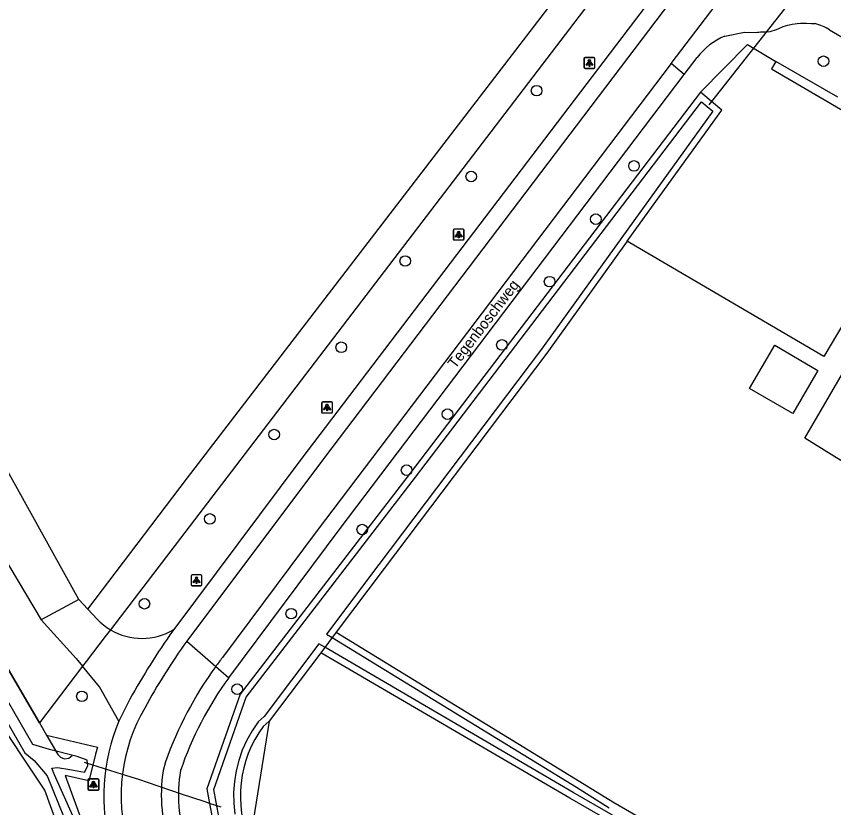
# Model space of a CAD drawing. Extents: x 156502 to 159074, y 384229 to 386094.
# Drawn here: x 157013.2 to 157088.8, y 385827.5 to 385900.5 of the extents above; entities that cross this region are included whole.
import ezdxf

# ---------------------------------------------------------------- set-up
doc = ezdxf.new("R2010")
doc.units = 0
for name, color, linetype in [('IMGEO_Berm_groen', 7, 'Continuous'), ('IMGEO_Berm_halfverhard', 7, 'Continuous'), ('IMGEO_Boom', 7, 'Continuous'), ('IMGEO_Duiker', 7, 'Continuous'), ('IMGEO_Erf', 7, 'Continuous'), ('IMGEO_Groenvoorziening', 7, 'Continuous'), ('IMGEO_Haag', 7, 'Continuous'), ('IMGEO_Hek', 7, 'Continuous'), ('IMGEO_Lichtpunt', 7, 'Continuous'), ('IMGEO_Loofbos', 7, 'Continuous'), ('IMGEO_Openbare_ruimte_label', 7, 'Continuous'), ('IMGEO_Pand', 7, 'Continuous'), ('IMGEO_Rijbaan_lokaal_gesloten', 7, 'Continuous'), ('IMGEO_Rijbaan_lokaal_halfverhard', 7, 'Continuous'), ('IMGEO_Waterloop', 7, 'Continuous')]:
    doc.layers.add(name, color=color, linetype=linetype)

msp = doc.modelspace()

# ---------------------------------------------------------------- linework, layer by layer
at = {"layer": 'IMGEO_Berm_groen'}
msp.add_lwpolyline([(157184.907, 386057.234), (157021.918, 385843.894)], dxfattribs=at)
at = {"layer": 'IMGEO_Berm_halfverhard'}
for points in [[(157188.566, 386055.162), (157076.319, 385908.026), (157039.623, 385859.739), (157027.777, 385843.918)], [(157032.855, 385839.465), (157043.149, 385853.233), (157074.946, 385895.192)]]:
    msp.add_lwpolyline(points, dxfattribs=at)
msp.add_arc((157039.111, 385828.542), 17.804, 157.16468, 195.80884, dxfattribs=at)
at = {"layer": 'IMGEO_Boom'}
for centre in [(157087.82, 385896.404), (157061.306, 385893.682), (157070.302, 385886.733), (157055.263, 385885.754), (157066.776, 385881.815), (157049.163, 385877.949), (157062.506, 385876.047), (157043.253, 385869.983), (157058.102, 385870.199), (157053.074, 385863.804), (157037.054, 385861.923), (157049.291, 385858.635), (157031.106, 385854.129), (157045.19, 385853.148), (157025.065, 385846.293), (157038.63, 385845.375), (157033.63, 385838.407), (157019.285, 385837.744)]:
    msp.add_circle(centre, 0.489, dxfattribs=at)
at = {"layer": 'IMGEO_Duiker'}
for points in [[(157094.166, 385913.916), (157093.864, 385913.531), (157090.745, 385909.563), (157082.608, 385899.211), (157077.479, 385892.687), (157077.23, 385892.37)], [(157032.147, 385827.513), (157031.672, 385827.668), (157031.084, 385827.859), (157030.686, 385827.989), (157029.45, 385828.392), (157028.575, 385828.678), (157026.335, 385829.441), (157024.544, 385830.051), (157023.026, 385830.525), (157020.689, 385831.254), (157020.295, 385831.377), (157019.534, 385831.625)]]:
    msp.add_lwpolyline(points, dxfattribs=at)
at = {"layer": 'IMGEO_Erf'}
msp.add_lwpolyline([(157069.688, 385879.771), (157062.244, 385869.451), (157047.224, 385849.55), (157042.786, 385843.67), (157065.314, 385829.887), (157068.346, 385827.983), (157173.435, 385767.228), (157172.677, 385766.006), (157064.372, 385828.327), (157041.356, 385841.775), (157036.588, 385835.458)], dxfattribs=at)
at = {"layer": 'IMGEO_Groenvoorziening'}
for points in [[(157019.844, 385845.786), (157029.054, 385857.935), (157071.087, 385912.699), (157180.634, 386056.206), (157157.667, 386069.213), (157141.859, 386060.718)], [(157015.352, 385835.3), (157000, 385861.546), (156954.711, 385939.318)], [(157076.448, 385893.546), (157080.786, 385897.944), (157083.416, 385896.387)], [(157076.448, 385893.546), (157049.627, 385858.357), (157033.907, 385837.957), (157030.83, 385829.194), (157031.084, 385827.859), (157032.23, 385821.835), (157037.896, 385808.02), (157042.738, 385795.688), (157045.399, 385797.293)], [(157069.688, 385879.771), (157078.432, 385891.893), (157077.479, 385892.687), (157076.448, 385893.546)], [(157105.837, 385870.09), (157092.904, 385877.624), (157087.856, 385869.139), (157069.928, 385879.631), (157069.688, 385879.771)], [(157019.342, 385840.522), (157015.352, 385835.3)], [(157015.352, 385835.3), (157016.015, 385834.166), (157020.718, 385833.042), (157020.555, 385832.399), (157020.295, 385831.377), (157019.932, 385829.949), (157017.732, 385830.418), (157029.334, 385798.749)], [(157036.588, 385835.458), (157034.974, 385825.476), (157048.314, 385802.061)], [(157036.041, 385834.964), (157036.588, 385835.458)]]:
    msp.add_lwpolyline(points, dxfattribs=at)
msp.add_arc((157044.63, 385828.574), 10.705, 143.35, 203.97313, dxfattribs=at)
at = {"layer": 'IMGEO_Haag'}
for points in [[(157083.416, 385896.387), (157083.012, 385895.697), (157110.374, 385879.708), (157105.763, 385871.809), (157093.618, 385878.818), (157093.206, 385878.142), (157106.141, 385870.607)], [(157089.134, 385893.087), (157083.416, 385896.387)]]:
    msp.add_lwpolyline(points, dxfattribs=at)
at = {"layer": 'IMGEO_Hek'}
for points in [[(157069.928, 385879.631), (157069.688, 385879.771)], [(157105.837, 385870.09), (157092.904, 385877.624), (157087.856, 385869.139), (157069.928, 385879.631)], [(157062.244, 385869.451), (157047.224, 385849.55)], [(157000, 385861.546), (157015.352, 385835.3)], [(157047.224, 385849.55), (157042.786, 385843.67)], [(157042.786, 385843.67), (157041.356, 385841.775)], [(157041.356, 385841.775), (157036.588, 385835.458)], [(157015.352, 385835.3), (157016.015, 385834.166)], [(157036.588, 385835.458), (157034.974, 385825.476), (157048.314, 385802.061)], [(157016.015, 385834.166), (157017.071, 385832.361)], [(157017.071, 385832.361), (157017.295, 385832.115), (157017.683, 385831.969), (157018.092, 385832.037), (157018.396, 385832.278)]]:
    msp.add_lwpolyline(points, dxfattribs=at)
at = {"layer": 'IMGEO_Lichtpunt'}
for p, q in [((157065.684, 385896.653), (157065.684, 385895.846)), ((157065.684, 385896.653), (157065.684, 385895.846)), ((157065.69, 385896.625), (157065.69, 385895.818)), ((157065.69, 385896.625), (157065.69, 385895.818)), ((157066.586, 385896.748), (157065.778, 385896.748)), ((157066.586, 385896.748), (157065.778, 385896.748)), ((157066.592, 385896.72), (157065.784, 385896.72)), ((157066.592, 385896.72), (157065.784, 385896.72)), ((157066.68, 385895.846), (157066.68, 385896.653)), ((157066.68, 385895.846), (157066.68, 385896.653)), ((157066.686, 385895.818), (157066.686, 385896.625)), ((157066.686, 385895.818), (157066.686, 385896.625)), ((157065.778, 385895.752), (157066.586, 385895.752)), ((157065.778, 385895.752), (157066.586, 385895.752)), ((157065.784, 385895.724), (157066.592, 385895.724)), ((157065.784, 385895.724), (157066.592, 385895.724)), ((157053.595, 385880.794), (157053.595, 385879.987)), ((157053.595, 385880.794), (157053.595, 385879.987)), ((157053.621, 385880.81), (157053.621, 385880.003)), ((157053.621, 385880.81), (157053.621, 385880.003)), ((157054.497, 385880.889), (157053.689, 385880.889)), ((157054.497, 385880.889), (157053.689, 385880.889)), ((157054.523, 385880.905), (157053.715, 385880.905)), ((157054.523, 385880.905), (157053.715, 385880.905)), ((157054.591, 385879.987), (157054.591, 385880.794)), ((157054.591, 385879.987), (157054.591, 385880.794)), ((157054.617, 385880.003), (157054.617, 385880.81)), ((157054.617, 385880.003), (157054.617, 385880.81)), ((157053.689, 385879.893), (157054.497, 385879.893)), ((157053.689, 385879.893), (157054.497, 385879.893)), ((157053.715, 385879.909), (157054.523, 385879.909)), ((157053.715, 385879.909), (157054.523, 385879.909)), ((157041.435, 385864.817), (157041.435, 385864.01)), ((157041.435, 385864.817), (157041.435, 385864.01)), ((157041.444, 385864.835), (157041.444, 385864.028)), ((157041.444, 385864.835), (157041.444, 385864.028)), ((157042.337, 385864.912), (157041.529, 385864.912)), ((157042.337, 385864.912), (157041.529, 385864.912)), ((157042.346, 385864.93), (157041.538, 385864.93)), ((157042.346, 385864.93), (157041.538, 385864.93)), ((157042.431, 385864.01), (157042.431, 385864.817)), ((157042.431, 385864.01), (157042.431, 385864.817)), ((157042.44, 385864.028), (157042.44, 385864.835)), ((157042.44, 385864.028), (157042.44, 385864.835)), ((157041.529, 385863.916), (157042.337, 385863.916)), ((157041.529, 385863.916), (157042.337, 385863.916)), ((157041.538, 385863.934), (157042.346, 385863.934)), ((157041.538, 385863.934), (157042.346, 385863.934)), ((157029.374, 385848.856), (157029.374, 385848.049)), ((157029.374, 385848.856), (157029.374, 385848.049)), ((157029.381, 385848.881), (157029.381, 385848.074)), ((157029.381, 385848.881), (157029.381, 385848.074)), ((157030.276, 385848.951), (157029.468, 385848.951)), ((157030.276, 385848.951), (157029.468, 385848.951)), ((157030.283, 385848.976), (157029.475, 385848.976)), ((157030.283, 385848.976), (157029.475, 385848.976)), ((157030.37, 385848.049), (157030.37, 385848.856)), ((157030.37, 385848.049), (157030.37, 385848.856)), ((157030.377, 385848.074), (157030.377, 385848.881)), ((157030.377, 385848.074), (157030.377, 385848.881)), ((157029.468, 385847.955), (157030.276, 385847.955)), ((157029.468, 385847.955), (157030.276, 385847.955)), ((157029.475, 385847.98), (157030.283, 385847.98)), ((157029.475, 385847.98), (157030.283, 385847.98)), ((157019.842, 385829.989), (157019.842, 385829.182)), ((157019.842, 385829.989), (157019.842, 385829.182)), ((157019.845, 385830.016), (157019.845, 385829.209)), ((157019.845, 385830.016), (157019.845, 385829.209)), ((157019.877, 385829.983), (157019.877, 385829.176)), ((157019.877, 385829.983), (157019.877, 385829.176)), ((157020.744, 385830.084), (157019.936, 385830.084)), ((157020.744, 385830.084), (157019.936, 385830.084)), ((157020.747, 385830.111), (157019.939, 385830.111)), ((157020.747, 385830.111), (157019.939, 385830.111)), ((157020.779, 385830.078), (157019.971, 385830.078)), ((157020.779, 385830.078), (157019.971, 385830.078)), ((157020.838, 385829.182), (157020.838, 385829.989)), ((157020.838, 385829.182), (157020.838, 385829.989)), ((157020.841, 385829.209), (157020.841, 385830.016)), ((157020.841, 385829.209), (157020.841, 385830.016)), ((157020.873, 385829.176), (157020.873, 385829.983)), ((157020.873, 385829.176), (157020.873, 385829.983)), ((157019.936, 385829.088), (157020.744, 385829.088)), ((157019.936, 385829.088), (157020.744, 385829.088)), ((157019.939, 385829.115), (157020.747, 385829.115)), ((157019.939, 385829.115), (157020.747, 385829.115)), ((157019.971, 385829.082), (157020.779, 385829.082)), ((157019.971, 385829.082), (157020.779, 385829.082))]:
    msp.add_line(p, q, dxfattribs=at)
for points in [[(157066.058, 385896.317), (157066.097, 385896.289), (157065.909, 385896.027), (157065.871, 385896.054), (157066.058, 385896.317)], [(157066.064, 385896.289), (157066.103, 385896.261), (157065.915, 385895.999), (157065.877, 385896.026), (157066.064, 385896.289)], [(157066.16, 385896.269), (157066.207, 385896.269), (157066.207, 385895.947), (157066.16, 385895.947), (157066.16, 385896.269)], [(157066.166, 385896.241), (157066.213, 385896.241), (157066.213, 385895.919), (157066.166, 385895.919), (157066.166, 385896.241)], [(157066.27, 385896.289), (157066.308, 385896.316), (157066.495, 385896.054), (157066.456, 385896.026), (157066.27, 385896.289)], [(157066.276, 385896.261), (157066.314, 385896.288), (157066.501, 385896.026), (157066.462, 385895.998), (157066.276, 385896.261)], [(157053.969, 385880.458), (157054.008, 385880.43), (157053.82, 385880.168), (157053.782, 385880.195), (157053.969, 385880.458)], [(157053.995, 385880.474), (157054.034, 385880.446), (157053.846, 385880.184), (157053.808, 385880.211), (157053.995, 385880.474)], [(157054.071, 385880.41), (157054.118, 385880.41), (157054.118, 385880.088), (157054.071, 385880.088), (157054.071, 385880.41)], [(157054.097, 385880.426), (157054.144, 385880.426), (157054.144, 385880.104), (157054.097, 385880.104), (157054.097, 385880.426)], [(157054.181, 385880.43), (157054.219, 385880.457), (157054.406, 385880.195), (157054.367, 385880.167), (157054.181, 385880.43)], [(157054.207, 385880.446), (157054.245, 385880.473), (157054.432, 385880.211), (157054.393, 385880.183), (157054.207, 385880.446)], [(157041.809, 385864.481), (157041.848, 385864.453), (157041.66, 385864.191), (157041.622, 385864.218), (157041.809, 385864.481)], [(157041.818, 385864.499), (157041.857, 385864.471), (157041.669, 385864.209), (157041.631, 385864.236), (157041.818, 385864.499)], [(157041.911, 385864.433), (157041.958, 385864.433), (157041.958, 385864.111), (157041.911, 385864.111), (157041.911, 385864.433)], [(157041.92, 385864.451), (157041.967, 385864.451), (157041.967, 385864.129), (157041.92, 385864.129), (157041.92, 385864.451)], [(157042.021, 385864.453), (157042.059, 385864.48), (157042.246, 385864.218), (157042.207, 385864.19), (157042.021, 385864.453)], [(157042.03, 385864.471), (157042.068, 385864.498), (157042.255, 385864.236), (157042.216, 385864.208), (157042.03, 385864.471)], [(157029.755, 385848.545), (157029.794, 385848.517), (157029.606, 385848.255), (157029.568, 385848.282), (157029.755, 385848.545)], [(157029.967, 385848.517), (157030.005, 385848.544), (157030.192, 385848.282), (157030.153, 385848.254), (157029.967, 385848.517)], [(157029.748, 385848.52), (157029.787, 385848.492), (157029.599, 385848.23), (157029.561, 385848.257), (157029.748, 385848.52)], [(157029.85, 385848.472), (157029.897, 385848.472), (157029.897, 385848.15), (157029.85, 385848.15), (157029.85, 385848.472)], [(157029.857, 385848.497), (157029.904, 385848.497), (157029.904, 385848.175), (157029.857, 385848.175), (157029.857, 385848.497)], [(157029.96, 385848.492), (157029.998, 385848.519), (157030.185, 385848.257), (157030.146, 385848.229), (157029.96, 385848.492)], [(157020.216, 385829.653), (157020.255, 385829.625), (157020.067, 385829.363), (157020.029, 385829.39), (157020.216, 385829.653)], [(157020.219, 385829.68), (157020.258, 385829.652), (157020.07, 385829.39), (157020.032, 385829.417), (157020.219, 385829.68)], [(157020.251, 385829.647), (157020.29, 385829.619), (157020.102, 385829.357), (157020.064, 385829.384), (157020.251, 385829.647)], [(157020.428, 385829.625), (157020.466, 385829.652), (157020.653, 385829.39), (157020.614, 385829.362), (157020.428, 385829.625)], [(157020.431, 385829.652), (157020.469, 385829.679), (157020.656, 385829.417), (157020.617, 385829.389), (157020.431, 385829.652)], [(157020.463, 385829.619), (157020.501, 385829.646), (157020.688, 385829.384), (157020.649, 385829.356), (157020.463, 385829.619)], [(157020.318, 385829.605), (157020.365, 385829.605), (157020.365, 385829.283), (157020.318, 385829.283), (157020.318, 385829.605)], [(157020.321, 385829.632), (157020.368, 385829.632), (157020.368, 385829.31), (157020.321, 385829.31), (157020.321, 385829.632)], [(157020.353, 385829.599), (157020.4, 385829.599), (157020.4, 385829.277), (157020.353, 385829.277), (157020.353, 385829.599)]]:
    msp.add_lwpolyline(points, dxfattribs=at)
for centre in [(157066.183, 385896.451), (157066.189, 385896.423), (157054.094, 385880.592), (157054.12, 385880.608), (157041.934, 385864.615), (157041.943, 385864.633), (157029.873, 385848.654), (157029.88, 385848.679), (157020.341, 385829.787), (157020.344, 385829.814), (157020.376, 385829.781)]:
    msp.add_circle(centre, 0.0994, dxfattribs=at)
for centre, start, end in [((157065.778, 385896.653), 90, 180), ((157065.778, 385896.653), 90, 180), ((157065.784, 385896.625), 90, 180), ((157065.784, 385896.625), 90, 180), ((157066.586, 385896.653), 0, 90), ((157066.586, 385896.653), 0, 90), ((157066.592, 385896.625), 0, 90), ((157066.592, 385896.625), 0, 90), ((157065.778, 385895.846), 180, 270), ((157065.778, 385895.846), 180, 270), ((157065.784, 385895.818), 180, 270), ((157065.784, 385895.818), 180, 270), ((157066.586, 385895.846), 270, 0), ((157066.586, 385895.846), 270, 360), ((157066.592, 385895.818), 270, 0), ((157066.592, 385895.818), 270, 360), ((157053.689, 385880.794), 90, 180), ((157053.689, 385880.794), 90, 180), ((157053.715, 385880.81), 90, 180), ((157053.715, 385880.81), 90, 180), ((157054.497, 385880.794), 0, 90), ((157054.497, 385880.794), 0, 90), ((157054.523, 385880.81), 0, 90), ((157054.523, 385880.81), 0, 90), ((157053.689, 385879.987), 180, 270), ((157053.689, 385879.987), 180, 270), ((157053.715, 385880.003), 180, 270), ((157053.715, 385880.003), 180, 270), ((157054.497, 385879.987), 270, 0), ((157054.497, 385879.987), 270, 360), ((157054.523, 385880.003), 270, 0), ((157054.523, 385880.003), 270, 360), ((157041.529, 385864.817), 90, 180), ((157041.529, 385864.817), 90, 180), ((157041.538, 385864.835), 90, 180), ((157041.538, 385864.835), 90, 180), ((157042.337, 385864.817), 0, 90), ((157042.337, 385864.817), 0, 90), ((157042.346, 385864.835), 0, 90), ((157042.346, 385864.835), 0, 90), ((157041.529, 385864.01), 180, 270), ((157041.529, 385864.01), 180, 270), ((157041.538, 385864.028), 180, 270), ((157041.538, 385864.028), 180, 270), ((157042.337, 385864.01), 270, 0), ((157042.337, 385864.01), 270, 360), ((157042.346, 385864.028), 270, 0), ((157042.346, 385864.028), 270, 360), ((157029.468, 385848.856), 90, 180), ((157029.468, 385848.856), 90, 180), ((157029.475, 385848.881), 90, 180), ((157029.475, 385848.881), 90, 180), ((157030.276, 385848.856), 0, 90), ((157030.276, 385848.856), 0, 90), ((157030.283, 385848.881), 0, 90), ((157030.283, 385848.881), 0, 90), ((157029.468, 385848.049), 180, 270), ((157029.468, 385848.049), 180, 270), ((157029.475, 385848.074), 180, 270), ((157029.475, 385848.074), 180, 270), ((157030.276, 385848.049), 270, 0), ((157030.276, 385848.049), 270, 360), ((157030.283, 385848.074), 270, 0), ((157030.283, 385848.074), 270, 360), ((157019.936, 385829.989), 90, 180), ((157019.936, 385829.989), 90, 180), ((157019.939, 385830.016), 90, 180), ((157019.939, 385830.016), 90, 180), ((157019.971, 385829.983), 90, 180), ((157019.971, 385829.983), 90, 180), ((157020.744, 385829.989), 0, 90), ((157020.744, 385829.989), 0, 90), ((157020.747, 385830.016), 0, 90), ((157020.747, 385830.016), 0, 90), ((157020.779, 385829.983), 0, 90), ((157020.779, 385829.983), 0, 90), ((157019.936, 385829.182), 180, 270), ((157019.936, 385829.182), 180, 270), ((157019.939, 385829.209), 180, 270), ((157019.939, 385829.209), 180, 270), ((157019.971, 385829.176), 180, 270), ((157019.971, 385829.176), 180, 270), ((157020.744, 385829.182), 270, 0), ((157020.744, 385829.182), 270, 360), ((157020.747, 385829.209), 270, 0), ((157020.747, 385829.209), 270, 360), ((157020.779, 385829.176), 270, 0), ((157020.779, 385829.176), 270, 360)]:
    msp.add_arc(centre, 0.0946, start, end, dxfattribs=at)
at = {"layer": 'IMGEO_Loofbos'}
msp.add_lwpolyline([(157027.141, 385797.89), (157015.854, 385829.061), (157010.805, 385836.629), (157000, 385855.161), (156976.182, 385896.012), (156952.047, 385938.123)], dxfattribs=at)
at = {"layer": 'IMGEO_Pand'}
for points in [[(157106.562, 385858.084), (157102.808, 385851.646), (157093.53, 385857.04), (157093.801, 385857.507), (157091.477, 385858.867), (157091.192, 385858.41), (157086.085, 385861.587), (157093.153, 385873.673), (157098.324, 385870.649), (157094.927, 385864.842), (157100.545, 385861.579)], [(157080.994, 385866.183), (157083.323, 385870.166), (157087.307, 385867.836), (157084.978, 385863.853), (157080.994, 385866.183)]]:
    msp.add_lwpolyline(points, dxfattribs=at)
at = {"layer": 'IMGEO_Rijbaan_lokaal_gesloten'}
for points in [[(157189.916, 386054.397), (157077.656, 385907.175), (157041.694, 385859.803), (157028.972, 385842.844)], [(156974.125, 385919.066), (156974.666, 385918.414), (156973.308, 385915.893), (156981.323, 385902.229), (157015.536, 385844.817)], [(157073.728, 385896.192), (157090.505, 385918.168)], [(157019.003, 385846.692), (157010.156, 385862.563), (156990.12, 385896.678), (156989.301, 385898.643), (156999.468, 385912.632)], [(157078.711, 385898.72), (157080.51, 385899.085), (157081.564, 385899.068), (157081.711, 385899.078), (157081.857, 385899.092), (157082.003, 385899.108), (157082.528, 385899.11), (157082.877, 385899.153), (157083.46, 385899.336), (157083.705, 385899.44), (157084.083, 385899.599), (157084.526, 385899.739), (157084.936, 385899.83), (157085.387, 385899.9), (157085.687, 385899.926), (157086.259, 385899.926), (157086.696, 385899.895), (157087.034, 385899.877)], [(157088.378, 385899.319), (157091.625, 385897.383)], [(157073.728, 385896.192), (157041.03, 385853.045), (157032.276, 385841.324)], [(157074.946, 385895.192), (157073.728, 385896.192)], [(157074.946, 385895.192), (157076.145, 385896.75)], [(157019.003, 385846.692), (157015.536, 385844.817)], [(157019.844, 385845.786), (157019.003, 385846.692)], [(157020.691, 385844.872), (157019.844, 385845.786)], [(157015.536, 385844.817), (157018.755, 385841.24), (157019.342, 385840.522)], [(157021.918, 385843.894), (157021.43, 385843.256), (157019.673, 385840.956), (157019.342, 385840.522)], [(157027.777, 385843.918), (157027.693, 385843.804)], [(157028.972, 385842.844), (157031.66, 385840.505)], [(157022.702, 385835.452), (157020.897, 385838.622), (157019.342, 385840.522)], [(157023.706, 385837.47), (157022.702, 385835.452)], [(157026.997, 385831.693), (157026.791, 385830.905)]]:
    msp.add_lwpolyline(points, dxfattribs=at)
for centre, radius, start, end in [((157085.798, 385895.003), 5.028, 59.1326, 75.77305), ((157081.05, 385893.017), 6.164, 112.30073, 142.72846), ((157024.858, 385848.842), 5.755, 223.60806, 239.27762), ((157024.827, 385848.799), 5.703, 239.32267, 301.14672), ((157081.501, 385805.512), 66.042, 144.5629, 151.05955), ((157081.578, 385805.472), 64.53, 144.61002, 151.0964), ((157058.866, 385820.684), 33.66, 142.1796, 143.92406), ((157059.747, 385820.002), 34.774, 143.87214, 160.35543), ((157039.128, 385828.54), 16.221, 149.95096, 195.52867), ((157041.52, 385828.676), 14.897, 171.39314, 199.61838)]:
    msp.add_arc(centre, radius, start, end, dxfattribs=at)
at = {"layer": 'IMGEO_Rijbaan_lokaal_halfverhard'}
msp.add_lwpolyline([(157031.66, 385840.505), (157032.855, 385839.465)], dxfattribs=at)
for centre, radius, start, end in [((157058.899, 385820.5), 32.218, 143.93907, 161.20917), ((157041.034, 385828.611), 12.837, 169.82625, 199.42679)]:
    msp.add_arc(centre, radius, start, end, dxfattribs=at)
at = {"layer": 'IMGEO_Waterloop'}
for points in [[(157018.567, 385826.419), (157016.741, 385830.496), (157016.521, 385831.102), (157017.025, 385831.176), (157018.173, 385830.972), (157019.528, 385830.75), (157019.826, 385831.333), (157019.787, 385831.843), (157018.852, 385832.194), (157016.284, 385832.826), (157014.754, 385833.309), (157006.405, 385847.723), (156983.301, 385887.463), (156952.185, 385940.336), (156951.867, 385940.354), (156951.504, 385940.095), (156951.123, 385939.652)], [(156951.435, 385939.137), (156952.022, 385939.384), (156952.452, 385938.78), (156975.353, 385899.502), (156981.399, 385889.178), (156992.799, 385869.326), (157014.016, 385832.518), (157014.887, 385831.813), (157016.071, 385830.387), (157018.182, 385825.214), (157027.558, 385798.454), (157028.583, 385795.802), (157028.993, 385793.594), (157029.286, 385791.31), (157029.321, 385788.288), (157028.581, 385767.902), (157027.471, 385744.333), (157025.899, 385729.166)], [(157032.829, 385822.013), (157031.759, 385827.64), (157031.695, 385827.975), (157031.473, 385829.146), (157034.461, 385837.656), (157050.121, 385857.979), (157076.549, 385892.652), (157077.081, 385892.209), (157077.588, 385891.786), (157069.183, 385880.135)], [(157069.183, 385880.135), (157061.743, 385869.82), (157046.727, 385849.925), (157041.876, 385843.497), (157042.409, 385843.171), (157064.986, 385829.358), (157068.025, 385827.45)], [(157172.466, 385766.846), (157064.684, 385828.865), (157041.733, 385842.275), (157041.192, 385842.591), (157036.127, 385835.88), (157035.579, 385835.385), (157035.012, 385834.558), (157034.521, 385833.685), (157034.109, 385832.771), (157033.779, 385831.824), (157033.534, 385830.852), (157033.376, 385829.862), (157033.306, 385828.862), (157033.325, 385827.86), (157033.432, 385826.863)]]:
    msp.add_lwpolyline(points, dxfattribs=at)

# ---------------------------------------------------------------- texts
at = {"layer": 'IMGEO_Openbare_ruimte_label'}
msp.add_text('Tegenboschweg', height=1, rotation=52.55716, dxfattribs=at).set_placement((157053.796, 385867.938))

doc.saveas('drawing.dxf')
